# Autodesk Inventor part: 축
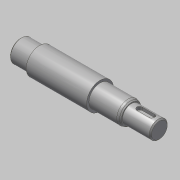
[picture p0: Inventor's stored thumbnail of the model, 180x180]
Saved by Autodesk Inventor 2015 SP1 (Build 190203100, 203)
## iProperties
Created: 2016-06
Part Number: 축
Material: 강철, 연강
Document SubType Name: Modeling
Designer: mduedu
Density: 7.86 g/cm^3
Appearance: 강철
Author: mduedu
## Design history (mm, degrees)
sketch "스케치1"
  geometry: L1 (-62, 0)-(62, 0); L2 (-62, 0)-(-62, 10); L3 (-62, 10)-(-45, 10); L4 (-45, 10)-(-45, 12); L5 (-45, 12)-(9, 12); L6 (9, 12)-(9, 10); L7 (9, 10)-(37, 10); L8 (37, 10)-(37, 8); L9 (37, 8)-(62, 8); L10 (62, 8)-(62, 0); 2 further points
  constraints: 20 end point, 5 parallel, 2 perpendicular, 1 coincident, 1 collinear, 1 horizontal, 1 midpoint, 1 vertical
  dimensions: "d0" = 124 distance of L1.start L1.end; "d2" = 16 diameter of L9 L1; "d3" = 20 diameter of L7 L1; "d4" = 24 diameter of L5 L1; "d5" = 20 diameter of L3 L1; "d6" = 17 distance of L2.end L3.end; "d7" = 25 distance of L8.end L9.end; "d8" = 53 distance from line of L5.end L10
revolve "회전1" sketch "스케치1" stored, may be unused: angle "d9" = 90 deg
chamfer "모따기1" distance "d10" = 2; stored, may be unused: second distance "d11" = 2, angle "d12" = 30 deg
fillet "모깎기1" dims "d13" = 4
node "작업 평면1"
sketch "스케치2"
  geometry: L1 (-5, 2.5)-(6, 2.5); L2 (6, -2.5)-(-5, -2.5); L3 (-5, 0)-(6, 0); L4 (-12.5, 8.845)-(-12.5, -8.845) reference; A1 r 2.5 centre (-5, 0) between (-5, 2.5) and (-5, -2.5); A2 r 2.5 centre (6, 0) between (6, -2.5) and (6, 2.5); 1 further point
  constraints: 6 end point, 4 point on circle, 3 tangent, 2 centre point, 2 parallel, 1 horizontal, 1 horizontal alignment
  dimensions: "d14" = 5 distance edge to line of A1 L4; "d15" = 5 distance between parallel lines of L2 L1; "d16" = 16 dimension on A2 A1
extrude "돌출1" cut sketch "스케치2" distance "d17" = 3; taper "d18" = 0 deg
chamfer "모따기2" distance "d19" = 1; stored, may be unused: second distance "d20" = 2, angle "d21" = 30 deg
sketch "스케치3"
  geometry: L1 (-37, -8)-(-61, -8) reference; L2 (-62, -7)-(-62, 7) reference; L3 (-38.5, -8)-(-40, -6.5); L4 (-40, -6.5)-(-40, -8); L5 (-38.5, -8)-(-40, -8); 1 further point
  constraints: 6 end point, 2 point on line, 1 collinear, 1 vertical
  dimensions: "d22" = 45 deg angle of L4 L3; "d23" = 22 distance between parallel lines of L2 L4; "d24" = 3 diameter of L3.start L4
revolve "회전2" stored, may be unused: angle "d25" = 90 deg
node "작업점1"
sketch "스케치4"
  geometry: 1 further point
hole "구멍1" sketch "스케치4" at (0, 0) diameter "d26" = 3.242; stored, may be unused: countersink angle "d30" = 90 deg, drill point angle "d32" = 120 deg; dims "d27" = 8, "d28" = 4, "d29" = 2, "d31" = 11
chamfer "모따기3" distance "d33" = 2; stored, may be unused: second distance "d34" = 2, angle "d35" = 30 deg
node "솔리드1"
